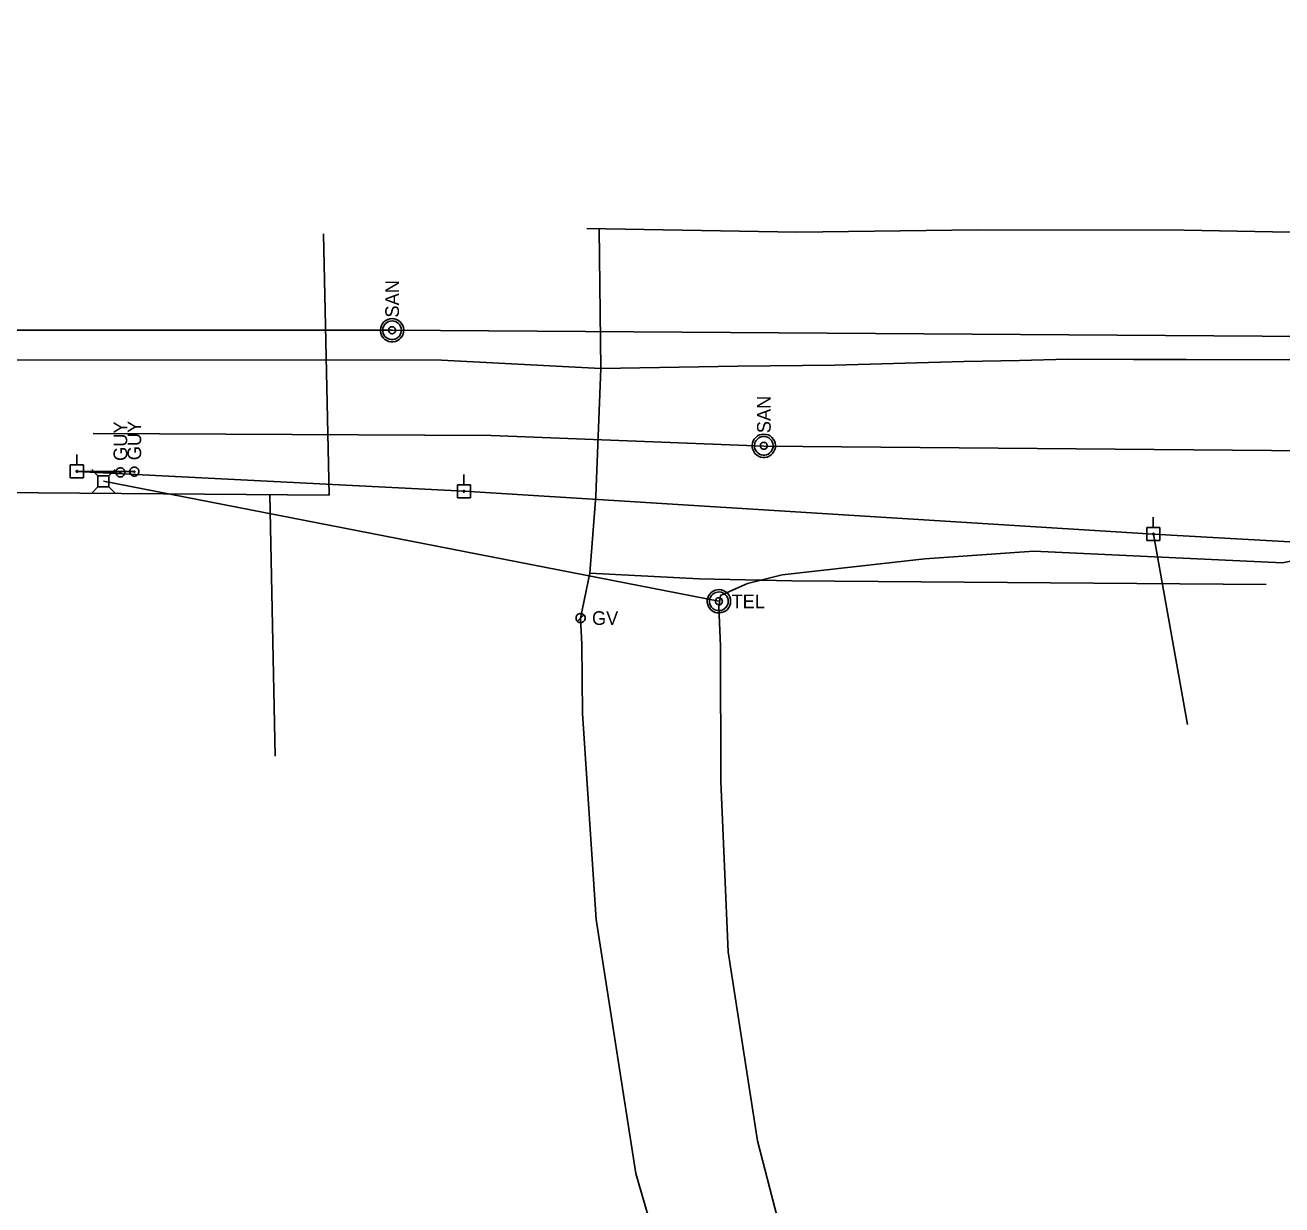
# Model space of a CAD drawing. Extents: x 600849 to 606371, y 330010 to 403088.
# Drawn here: x 601339.3 to 601694.1, y 355310.5 to 355643.5 of the extents above; entities that cross this region are included whole.
import ezdxf

# ---------------------------------------------------------------- set-up
doc = ezdxf.new("R2010")
doc.units = 0
for name, color, linetype in [('E_UTL_AG_Bold', 7, 'Continuous'), ('E_UTL_EGuyWire', 7, 'Continuous'), ('E_UTL_EPowerPole', 7, 'Continuous'), ('E_UTL_G', 7, 'Continuous'), ('E_UTL_G_UG', 7, 'Continuous'), ('E_UTL_Overhead', 7, 'Continuous'), ('E_UTL_SAN', 7, 'Continuous'), ('E_UTL_SAN_UG', 7, 'Continuous'), ('E_UTL_T_MH', 7, 'Continuous'), ('E_UTL_T_UG', 7, 'Continuous')]:
    doc.layers.add(name, color=color, linetype=linetype)

msp = doc.modelspace()

# ---------------------------------------------------------------- linework, layer by layer
at = {"layer": 'E_UTL_AG_Bold'}
for points in [[(601359.83, 355516.25), (601358.07, 355518.01)], [(601362.92, 355516.25), (601364.67, 355518.01)], [(601362.92, 355516.25), (601359.83, 355516.25)], [(601359.83, 355516.25), (601359.83, 355513.16)], [(601362.92, 355513.16), (601362.92, 355516.25)], [(601359.83, 355513.16), (601358.07, 355511.41)], [(601359.83, 355513.16), (601362.92, 355513.16)], [(601362.92, 355513.16), (601364.67, 355511.41)]]:
    msp.add_lwpolyline(points, dxfattribs=at)
at = {"layer": 'E_UTL_EGuyWire'}
for p in [(601366.18, 355517.25), (601370.12, 355517.44)]:
    msp.add_line(p, (601353.91, 355517.52), dxfattribs=at)
for points in [[(601366.18, 355518.53), (601365.94, 355518.51), (601365.7, 355518.44), (601365.48, 355518.33), (601365.29, 355518.18), (601365.13, 355517.99), (601365.01, 355517.78), (601364.93, 355517.55), (601364.9, 355517.31), (601364.91, 355517.06), (601364.97, 355516.83), (601365.07, 355516.61), (601365.21, 355516.41), (601365.38, 355516.24), (601365.59, 355516.11), (601365.82, 355516.02), (601366.06, 355515.97), (601366.3, 355515.97), (601366.54, 355516.02), (601366.77, 355516.11), (601366.97, 355516.24), (601367.15, 355516.41), (601367.29, 355516.61), (601367.39, 355516.83), (601367.45, 355517.06), (601367.46, 355517.31), (601367.43, 355517.55), (601367.35, 355517.78), (601367.22, 355517.99), (601367.06, 355518.18), (601366.87, 355518.33), (601366.66, 355518.44), (601366.42, 355518.51), (601366.18, 355518.53)], [(601370.12, 355518.72), (601369.87, 355518.7), (601369.64, 355518.63), (601369.42, 355518.52), (601369.23, 355518.37), (601369.07, 355518.18), (601368.95, 355517.97), (601368.87, 355517.74), (601368.84, 355517.5), (601368.85, 355517.26), (601368.9, 355517.02), (601369.01, 355516.8), (601369.15, 355516.6), (601369.32, 355516.43), (601369.53, 355516.3), (601369.76, 355516.21), (601370, 355516.16), (601370.24, 355516.16), (601370.48, 355516.21), (601370.71, 355516.3), (601370.91, 355516.43), (601371.09, 355516.6), (601371.23, 355516.8), (601371.33, 355517.02), (601371.39, 355517.26), (601371.4, 355517.5), (601371.36, 355517.74), (601371.28, 355517.97), (601371.16, 355518.18), (601371, 355518.37), (601370.81, 355518.52), (601370.59, 355518.63), (601370.36, 355518.7), (601370.12, 355518.72)], [(601366.18, 355517.41), (601366.15, 355517.4), (601366.12, 355517.4), (601366.09, 355517.38), (601366.07, 355517.36), (601366.05, 355517.34), (601366.03, 355517.31), (601366.02, 355517.28), (601366.02, 355517.25), (601366.02, 355517.22), (601366.03, 355517.19), (601366.04, 355517.17), (601366.06, 355517.14), (601366.08, 355517.12), (601366.1, 355517.1), (601366.13, 355517.09), (601366.16, 355517.09), (601366.19, 355517.09), (601366.22, 355517.09), (601366.25, 355517.1), (601366.28, 355517.12), (601366.3, 355517.14), (601366.32, 355517.17), (601366.33, 355517.19), (601366.34, 355517.22), (601366.34, 355517.25), (601366.33, 355517.28), (601366.32, 355517.31), (601366.31, 355517.34), (601366.29, 355517.36), (601366.26, 355517.38), (601366.24, 355517.4), (601366.21, 355517.4), (601366.18, 355517.41)], [(601370.12, 355517.6), (601370.09, 355517.6), (601370.06, 355517.59), (601370.03, 355517.57), (601370.01, 355517.56), (601369.99, 355517.53), (601369.97, 355517.51), (601369.96, 355517.48), (601369.96, 355517.45), (601369.96, 355517.42), (601369.97, 355517.39), (601369.98, 355517.36), (601370, 355517.33), (601370.02, 355517.31), (601370.04, 355517.3), (601370.07, 355517.29), (601370.1, 355517.28), (601370.13, 355517.28), (601370.16, 355517.29), (601370.19, 355517.3), (601370.22, 355517.31), (601370.24, 355517.33), (601370.26, 355517.36), (601370.27, 355517.39), (601370.28, 355517.42), (601370.28, 355517.45), (601370.27, 355517.48), (601370.26, 355517.51), (601370.25, 355517.53), (601370.23, 355517.56), (601370.2, 355517.57), (601370.18, 355517.59), (601370.15, 355517.6), (601370.12, 355517.6)]]:
    msp.add_lwpolyline(points, dxfattribs=at)
at = {"layer": 'E_UTL_EPowerPole'}
for points in [[(601353.88, 355519.37), (601353.88, 355522.27)], [(601355.72, 355519.37), (601352.04, 355519.37)], [(601352.04, 355519.37), (601352.04, 355515.67)], [(601355.72, 355515.67), (601355.72, 355519.37)], [(601352.04, 355515.67), (601355.72, 355515.67)], [(601354.15, 355517.52), (601354.15, 355517.57), (601354.13, 355517.61), (601354.11, 355517.65), (601354.08, 355517.69), (601354.05, 355517.72), (601354.01, 355517.74), (601353.97, 355517.75), (601353.92, 355517.76), (601353.88, 355517.76), (601353.83, 355517.75), (601353.79, 355517.73), (601353.76, 355517.7), (601353.72, 355517.67), (601353.7, 355517.63), (601353.68, 355517.59), (601353.67, 355517.55), (601353.67, 355517.5), (601353.68, 355517.46), (601353.7, 355517.41), (601353.72, 355517.38), (601353.76, 355517.34), (601353.79, 355517.32), (601353.83, 355517.3), (601353.88, 355517.29), (601353.92, 355517.28), (601353.97, 355517.29), (601354.01, 355517.31), (601354.05, 355517.33), (601354.08, 355517.36), (601354.11, 355517.39), (601354.13, 355517.43), (601354.15, 355517.48), (601354.15, 355517.52)], [(601463.15, 355513.73), (601463.15, 355516.64)], [(601465, 355513.73), (601461.31, 355513.73)], [(601461.31, 355513.73), (601461.31, 355510.04)], [(601463.42, 355511.89), (601463.42, 355511.93), (601463.41, 355511.98), (601463.39, 355512.02), (601463.36, 355512.05), (601463.32, 355512.08), (601463.28, 355512.11), (601463.24, 355512.12), (601463.2, 355512.13), (601463.15, 355512.13), (601463.11, 355512.12), (601463.07, 355512.1), (601463.03, 355512.07), (601463, 355512.04), (601462.97, 355512), (601462.96, 355511.96), (601462.95, 355511.91), (601462.95, 355511.87), (601462.96, 355511.82), (601462.97, 355511.78), (601463, 355511.74), (601463.03, 355511.71), (601463.07, 355511.68), (601463.11, 355511.66), (601463.15, 355511.65), (601463.2, 355511.65), (601463.24, 355511.66), (601463.28, 355511.67), (601463.32, 355511.7), (601463.36, 355511.73), (601463.39, 355511.76), (601463.41, 355511.8), (601463.42, 355511.84), (601463.42, 355511.89)], [(601465, 355510.04), (601465, 355513.73)], [(601461.31, 355510.04), (601465, 355510.04)], [(601657.8, 355501.66), (601657.8, 355504.57)], [(601659.65, 355501.66), (601655.96, 355501.66)], [(601655.96, 355501.66), (601655.96, 355497.97)], [(601659.65, 355497.97), (601659.65, 355501.66)], [(601655.96, 355497.97), (601659.65, 355497.97)], [(601658.07, 355499.82), (601658.07, 355499.86), (601658.06, 355499.91), (601658.04, 355499.95), (601658.01, 355499.98), (601657.97, 355500.01), (601657.93, 355500.03), (601657.89, 355500.05), (601657.85, 355500.06), (601657.8, 355500.05), (601657.76, 355500.04), (601657.72, 355500.02), (601657.68, 355500), (601657.65, 355499.97), (601657.62, 355499.93), (601657.61, 355499.89), (601657.6, 355499.84), (601657.6, 355499.8), (601657.61, 355499.75), (601657.62, 355499.71), (601657.65, 355499.67), (601657.68, 355499.64), (601657.72, 355499.61), (601657.76, 355499.59), (601657.8, 355499.58), (601657.85, 355499.58), (601657.89, 355499.59), (601657.93, 355499.6), (601657.97, 355499.62), (601658.01, 355499.65), (601658.04, 355499.69), (601658.06, 355499.73), (601658.07, 355499.77), (601658.07, 355499.82)]]:
    msp.add_lwpolyline(points, dxfattribs=at)
at = {"layer": 'E_UTL_G'}
for points in [[(601497.39, 355476.1), (601497.36, 355476.35), (601497.29, 355476.58), (601497.18, 355476.8), (601497.03, 355476.99), (601496.85, 355477.15), (601496.64, 355477.27), (601496.4, 355477.35), (601496.16, 355477.38), (601495.92, 355477.37), (601495.68, 355477.32), (601495.46, 355477.21), (601495.26, 355477.07), (601495.09, 355476.9), (601494.96, 355476.69), (601494.87, 355476.46), (601494.82, 355476.23), (601494.82, 355475.98), (601494.87, 355475.74), (601494.96, 355475.51), (601495.09, 355475.31), (601495.26, 355475.13), (601495.46, 355474.99), (601495.68, 355474.89), (601495.92, 355474.83), (601496.16, 355474.82), (601496.4, 355474.86), (601496.64, 355474.94), (601496.85, 355475.06), (601497.03, 355475.22), (601497.18, 355475.41), (601497.29, 355475.63), (601497.36, 355475.86), (601497.39, 355476.1)], [(601495.19, 355475.2), (601497.01, 355477.01)]]:
    msp.add_lwpolyline(points, dxfattribs=at)
at = {"layer": 'E_UTL_G_UG'}
for p, q in [((601425.08, 355510.76), (601423.54, 355584.59)), ((601280.68, 355511.94), (601425.08, 355510.76)), ((601409.88, 355437.11), (601408.34, 355510.9)), ((601555.79, 355486.63), (601689.63, 355485.59))]:
    msp.add_line(p, q, dxfattribs=at)
for points in [[(601497.89, 355586.04), (601557.2, 355585.04), (601608.23, 355585.72), (601666.55, 355585.63), (601741.3, 355584.2), (601771.33, 355584.5), (601794.45, 355589.66), (601806.2, 355637.49), (601811.35, 355665.27), (601815.89, 355691.42), (601823.98, 355737.46), (601828.35, 355766.99)], [(601501.38, 355585.93), (601501.85, 355546.55), (601500.39, 355510.6), (601498.67, 355488.82), (601529.59, 355487.14), (601555.79, 355486.63)], [(601281.11, 355548.99), (601456.8, 355548.88), (601501.85, 355546.55), (601540.47, 355547.26), (601567.93, 355547.51), (601604.28, 355548.55), (601619.98, 355548.78), (601633.71, 355549.19), (601652.23, 355549.07), (601667.06, 355549.06), (601732.27, 355548.91), (601793.04, 355547.03), (601830.3, 355547.67), (601851.95, 355547.88)], [(602084.88, 354419.03), (602050.79, 354491.49), (601978, 354610.16), (601921.16, 354689.22), (601864.82, 354766.45), (601805.94, 354849.01), (601742.46, 354936.76), (601698.09, 354996.25), (601671.25, 355033.27), (601606.99, 355120.49), (601573.46, 355165.54), (601553.19, 355205.28), (601531.03, 355252.86), (601511.69, 355319.31), (601500.48, 355391.06), (601496.69, 355449.14), (601496.48, 355468.72), (601496.1, 355476.1), (601498.67, 355488.82)]]:
    msp.add_lwpolyline(points, dxfattribs=at)
at = {"layer": 'E_UTL_Overhead'}
for points in [[(601353.91, 355517.52), (601463.19, 355511.89), (601657.83, 355499.82), (601775.11, 355493.17)], [(601657.83, 355499.82), (601667.44, 355446.07)]]:
    msp.add_lwpolyline(points, dxfattribs=at)
at = {"layer": 'E_UTL_SAN'}
for points in [[(601442.88, 355560.65), (601442.25, 355560.59), (601441.65, 355560.42), (601441.09, 355560.13), (601440.6, 355559.74), (601440.19, 355559.27), (601439.88, 355558.73), (601439.67, 355558.13), (601439.58, 355557.51), (601439.61, 355556.88), (601439.76, 355556.28), (601440.02, 355555.7), (601440.38, 355555.19), (601440.84, 355554.76), (601441.37, 355554.42), (601441.95, 355554.19), (601442.57, 355554.07), (601443.19, 355554.07), (601443.81, 355554.19), (601444.39, 355554.42), (601444.92, 355554.76), (601445.37, 355555.19), (601445.74, 355555.7), (601446, 355556.28), (601446.15, 355556.88), (601446.18, 355557.51), (601446.09, 355558.13), (601445.88, 355558.73), (601445.57, 355559.27), (601445.16, 355559.74), (601444.66, 355560.13), (601444.11, 355560.42), (601443.5, 355560.59), (601442.88, 355560.65)], [(601442.88, 355559.99), (601442.38, 355559.95), (601441.9, 355559.81), (601441.45, 355559.58), (601441.06, 355559.27), (601440.73, 355558.89), (601440.48, 355558.45), (601440.31, 355557.98), (601440.24, 355557.48), (601440.27, 355556.98), (601440.38, 355556.49), (601440.59, 355556.03), (601440.88, 355555.63), (601441.25, 355555.28), (601441.67, 355555.01), (601442.14, 355554.82), (601442.63, 355554.73), (601443.13, 355554.73), (601443.62, 355554.82), (601444.09, 355555.01), (601444.51, 355555.28), (601444.87, 355555.63), (601445.17, 355556.03), (601445.37, 355556.49), (601445.49, 355556.98), (601445.52, 355557.48), (601445.44, 355557.98), (601445.28, 355558.45), (601445.03, 355558.89), (601444.7, 355559.27), (601444.31, 355559.58), (601443.86, 355559.81), (601443.38, 355559.95), (601442.88, 355559.99)], [(601442.88, 355558.34), (601442.69, 355558.33), (601442.51, 355558.27), (601442.34, 355558.19), (601442.2, 355558.07), (601442.07, 355557.93), (601441.98, 355557.77), (601441.92, 355557.59), (601441.89, 355557.4), (601441.9, 355557.21), (601441.94, 355557.03), (601442.02, 355556.86), (601442.13, 355556.71), (601442.27, 355556.58), (601442.43, 355556.47), (601442.6, 355556.4), (601442.78, 355556.37), (601442.97, 355556.37), (601443.16, 355556.4), (601443.33, 355556.47), (601443.49, 355556.58), (601443.63, 355556.71), (601443.74, 355556.86), (601443.81, 355557.03), (601443.86, 355557.21), (601443.87, 355557.4), (601443.84, 355557.59), (601443.78, 355557.77), (601443.69, 355557.93), (601443.56, 355558.07), (601443.41, 355558.19), (601443.25, 355558.27), (601443.07, 355558.33), (601442.88, 355558.34)], [(601547.83, 355528.03), (601547.21, 355527.97), (601546.61, 355527.79), (601546.05, 355527.51), (601545.55, 355527.12), (601545.14, 355526.64), (601544.83, 355526.1), (601544.62, 355525.51), (601544.54, 355524.89), (601544.57, 355524.26), (601544.71, 355523.65), (601544.97, 355523.08), (601545.34, 355522.57), (601545.79, 355522.14), (601546.32, 355521.8), (601546.9, 355521.56), (601547.52, 355521.44), (601548.15, 355521.44), (601548.76, 355521.56), (601549.34, 355521.8), (601549.87, 355522.14), (601550.33, 355522.57), (601550.69, 355523.08), (601550.95, 355523.65), (601551.1, 355524.26), (601551.13, 355524.89), (601551.04, 355525.51), (601550.83, 355526.1), (601550.52, 355526.64), (601550.11, 355527.12), (601549.62, 355527.51), (601549.06, 355527.79), (601548.46, 355527.97), (601547.83, 355528.03)], [(601547.83, 355527.37), (601547.33, 355527.32), (601546.85, 355527.18), (601546.4, 355526.95), (601546.01, 355526.64), (601545.68, 355526.26), (601545.43, 355525.83), (601545.27, 355525.35), (601545.19, 355524.86), (601545.22, 355524.35), (601545.34, 355523.87), (601545.55, 355523.41), (601545.84, 355523), (601546.2, 355522.65), (601546.62, 355522.38), (601547.09, 355522.2), (601547.58, 355522.1), (601548.08, 355522.1), (601548.58, 355522.2), (601549.04, 355522.38), (601549.46, 355522.65), (601549.83, 355523), (601550.12, 355523.41), (601550.33, 355523.87), (601550.44, 355524.35), (601550.47, 355524.86), (601550.4, 355525.35), (601550.23, 355525.83), (601549.98, 355526.26), (601549.65, 355526.64), (601549.26, 355526.95), (601548.81, 355527.18), (601548.33, 355527.32), (601547.83, 355527.37)], [(601547.83, 355525.72), (601547.64, 355525.7), (601547.46, 355525.65), (601547.3, 355525.56), (601547.15, 355525.45), (601547.03, 355525.3), (601546.93, 355525.14), (601546.87, 355524.96), (601546.84, 355524.78), (601546.85, 355524.59), (601546.9, 355524.41), (601546.97, 355524.23), (601547.08, 355524.08), (601547.22, 355523.95), (601547.38, 355523.85), (601547.55, 355523.78), (601547.74, 355523.74), (601547.93, 355523.74), (601548.11, 355523.78), (601548.29, 355523.85), (601548.44, 355523.95), (601548.58, 355524.08), (601548.69, 355524.23), (601548.77, 355524.41), (601548.81, 355524.59), (601548.82, 355524.78), (601548.79, 355524.96), (601548.73, 355525.14), (601548.64, 355525.3), (601548.51, 355525.45), (601548.37, 355525.56), (601548.2, 355525.65), (601548.02, 355525.7), (601547.83, 355525.72)]]:
    msp.add_lwpolyline(points, dxfattribs=at)
at = {"layer": 'E_UTL_SAN_UG'}
for p, q in [((601168.48, 355557.35), (601442.88, 355557.35)), ((601442.88, 355557.35), (601777.6, 355555.11)), ((601547.86, 355524.61), (601862.49, 355521.89))]:
    msp.add_line(p, q, dxfattribs=at)
msp.add_lwpolyline([(601358.45, 355528.19), (601470.84, 355527.67), (601547.86, 355524.61)], dxfattribs=at)
at = {"layer": 'E_UTL_T_MH'}
for points in [[(601538.45, 355480.84), (601538.39, 355481.47), (601538.22, 355482.07), (601537.93, 355482.63), (601537.54, 355483.12), (601537.07, 355483.53), (601536.52, 355483.84), (601535.93, 355484.05), (601535.31, 355484.14), (601534.68, 355484.11), (601534.07, 355483.96), (601533.5, 355483.7), (601532.99, 355483.34), (601532.56, 355482.88), (601532.22, 355482.36), (601531.99, 355481.77), (601531.87, 355481.16), (601531.87, 355480.53), (601531.99, 355479.91), (601532.22, 355479.33), (601532.56, 355478.8), (601532.99, 355478.35), (601533.5, 355477.99), (601534.07, 355477.72), (601534.68, 355477.58), (601535.31, 355477.55), (601535.93, 355477.64), (601536.52, 355477.84), (601537.07, 355478.16), (601537.54, 355478.57), (601537.93, 355479.06), (601538.22, 355479.62), (601538.39, 355480.22), (601538.45, 355480.84)], [(601537.79, 355480.84), (601537.74, 355481.34), (601537.6, 355481.82), (601537.37, 355482.27), (601537.06, 355482.66), (601536.68, 355482.99), (601536.25, 355483.24), (601535.78, 355483.41), (601535.28, 355483.48), (601534.78, 355483.46), (601534.29, 355483.34), (601533.83, 355483.13), (601533.42, 355482.84), (601533.08, 355482.48), (601532.81, 355482.05), (601532.62, 355481.59), (601532.52, 355481.09), (601532.52, 355480.59), (601532.62, 355480.1), (601532.81, 355479.63), (601533.08, 355479.21), (601533.42, 355478.85), (601533.83, 355478.56), (601534.29, 355478.35), (601534.78, 355478.23), (601535.28, 355478.21), (601535.78, 355478.28), (601536.25, 355478.44), (601536.68, 355478.69), (601537.06, 355479.02), (601537.37, 355479.42), (601537.6, 355479.86), (601537.74, 355480.34), (601537.79, 355480.84)], [(601536.14, 355480.84), (601536.12, 355481.03), (601536.07, 355481.21), (601535.99, 355481.38), (601535.87, 355481.53), (601535.73, 355481.65), (601535.56, 355481.74), (601535.39, 355481.81), (601535.2, 355481.83), (601535.01, 355481.82), (601534.83, 355481.78), (601534.66, 355481.7), (601534.5, 355481.59), (601534.37, 355481.46), (601534.27, 355481.3), (601534.2, 355481.12), (601534.17, 355480.94), (601534.17, 355480.75), (601534.2, 355480.56), (601534.27, 355480.39), (601534.37, 355480.23), (601534.5, 355480.09), (601534.66, 355479.99), (601534.83, 355479.91), (601535.01, 355479.86), (601535.2, 355479.85), (601535.39, 355479.88), (601535.56, 355479.94), (601535.73, 355480.04), (601535.87, 355480.16), (601535.99, 355480.31), (601536.07, 355480.48), (601536.12, 355480.66), (601536.14, 355480.84)]]:
    msp.add_lwpolyline(points, dxfattribs=at)
at = {"layer": 'E_UTL_T_UG'}
for points in [[(601555.15, 355293.25), (601546.07, 355328.55), (601537.79, 355381.85), (601535.72, 355429.97), (601535.59, 355468.25), (601535.1, 355479.19), (601535.6, 355482.46), (601543.19, 355485.84), (601553.05, 355488.3), (601593.31, 355492.85), (601624.11, 355494.98), (601694.31, 355491.72), (601734.08, 355499.88), (601743.92, 355509.01), (601770.57, 355533.15), (601786.55, 355562.19), (601794.99, 355631.11), (601804.92, 355661.67), (601832.53, 355819.68), (601858.24, 355964.25), (601877.3, 356057.56)], [(601361.37, 355514.71), (601535.15, 355480.84)]]:
    msp.add_lwpolyline(points, dxfattribs=at)

# ---------------------------------------------------------------- texts
at = {"layer": 'E_UTL_EGuyWire'}
for p in [(601368.1, 355520.46), (601372.04, 355520.65)]:
    msp.add_text('GUY', height=3.85, rotation=90, dxfattribs=at).set_placement(p)
at = {"layer": 'E_UTL_G'}
msp.add_text('GV', height=3.85, dxfattribs=at).set_placement((601499.31, 355474.18))
at = {"layer": 'E_UTL_SAN'}
for p in [(601444.82, 355560.92), (601549.78, 355528.29)]:
    msp.add_text('SAN', height=3.849, rotation=90, dxfattribs=at).set_placement(p)
at = {"layer": 'E_UTL_T_MH'}
msp.add_text('TEL', height=3.849, dxfattribs=at).set_placement((601538.72, 355478.9))

doc.saveas('drawing.dxf')
